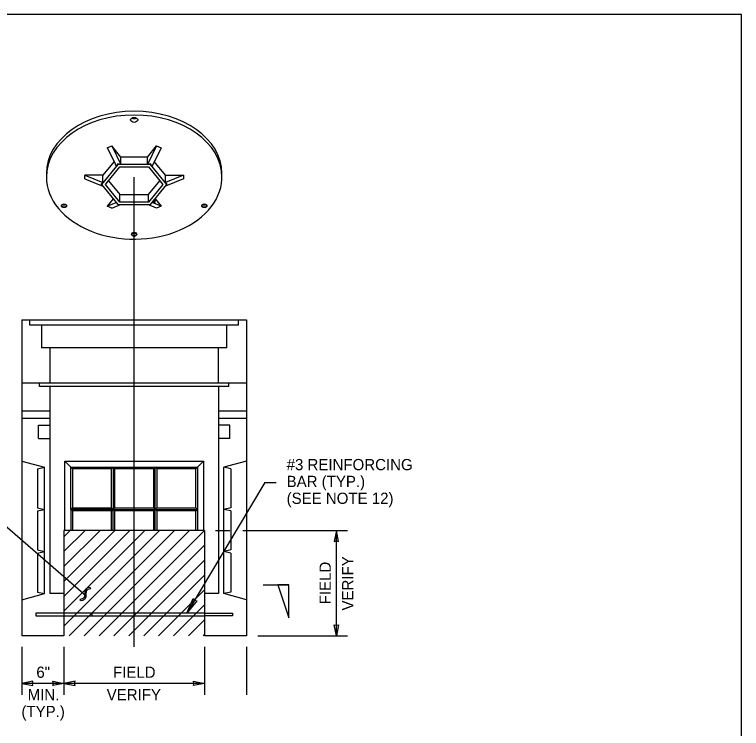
# Model space of a CAD drawing. Extents: x 99862 to 103151, y 100000 to 105076.
# Drawn here: x 102116 to 103151, y 104058 to 105076 of the extents above; entities that cross this region are included whole.
import ezdxf

# ---------------------------------------------------------------- set-up
doc = ezdxf.new("R2010")
doc.units = 0
for name, color, linetype in [('Level 1', 7, 'Continuous'), ('Level 10', 7, 'Continuous'), ('Level 12', 7, 'Continuous'), ('Level 14', 7, 'Continuous'), ('Level 15', 7, 'Continuous'), ('Level 2', 7, 'Continuous'), ('Level 20', 7, 'Continuous'), ('Level 21', 7, 'Continuous'), ('Level 3', 7, 'Continuous'), ('Level 60', 7, 'Continuous')]:
    doc.layers.add(name, color=color, linetype=linetype)

msp = doc.modelspace()

# ---------------------------------------------------------------- linework, layer by layer
at = {"layer": 'Level 1'}
msp.add_lwpolyline([(99862, 102999.5), (103151, 102999.5), (103151, 105075.5), (99862, 105075.5)], close=True, dxfattribs=at)
at = {"layer": 'Level 10'}
for p, q in [((102126.2, 104640.5), (102126.2, 104550.5)), ((102126.2, 104640.5), (102446.2, 104640.5)), ((102137.5, 104633), (102137.5, 104640.5)), ((102435, 104633), (102435, 104640.5)), ((102446.2, 104640.5), (102446.2, 104550.5)), ((102435, 104633), (102137.5, 104633)), ((102154.4, 104633), (102154.4, 104600.5)), ((102418.1, 104600.5), (102418.1, 104633)), ((102418.1, 104600.5), (102154.4, 104600.5)), ((102166.2, 104600.5), (102166.2, 104550.5)), ((102406.2, 104550.5), (102406.2, 104600.5)), ((102151.2, 104545.5), (102151.2, 104550.5)), ((102421.2, 104545.5), (102421.2, 104550.5)), ((102421.2, 104545.5), (102151.2, 104545.5))]:
    msp.add_line(p, q, dxfattribs=at)
at = {"layer": 'Level 12'}
for p, q in [((102247.9, 104885.5), (102254.4, 104888.2)), ((102247.9, 104885.5), (102257.5, 104865.9)), ((102267.2, 104872.5), (102254.4, 104888.2)), ((102254.4, 104888.2), (102267.2, 104862)), ((102305.2, 104872.5), (102318, 104888.2)), ((102318, 104888.2), (102305.2, 104862)), ((102324.5, 104885.5), (102311.7, 104859.3)), ((102318, 104888.2), (102324.5, 104885.5)), ((102267.2, 104862), (102267.2, 104872.5)), ((102305.2, 104872.5), (102267.2, 104872.5)), ((102305.2, 104862), (102305.2, 104872.5)), ((102262.9, 104861.9), (102239.6, 104833.3)), ((102257.5, 104865.9), (102241.8, 104846.6)), ((102257.5, 104865.9), (102260.7, 104859.3)), ((102262.9, 104862.9), (102260.7, 104859.3)), ((102262.9, 104861.9), (102262.9, 104862.9)), ((102267.2, 104862), (102262.9, 104862.9)), ((102309.5, 104861.9), (102262.9, 104861.9)), ((102309.5, 104862.9), (102305.2, 104862)), ((102311.7, 104859.3), (102309.5, 104862.9)), ((102309.5, 104861.9), (102309.5, 104862.9)), ((102332.9, 104833.3), (102309.5, 104861.9)), ((102330.7, 104846.6), (102314.9, 104865.9)), ((102245.4, 104833.3), (102265.8, 104858.3)), ((102265.8, 104858.3), (102306.7, 104858.3)), ((102306.7, 104858.3), (102327.1, 104833.3)), ((102161.2, 104849.2), (102161.2, 104843.9)), ((102216.1, 104841.3), (102216.1, 104846.6)), ((102241.8, 104846.6), (102216.1, 104846.6)), ((102216.1, 104846.6), (102241.8, 104836.1)), ((102216.1, 104841.3), (102241.6, 104830.9)), ((102241.8, 104836.1), (102241.8, 104846.6)), ((102356.3, 104846.6), (102330.7, 104836.1)), ((102330.7, 104836.1), (102330.7, 104846.6)), ((102330.7, 104846.6), (102356.3, 104846.6)), ((102356.3, 104841.3), (102330.9, 104830.9)), ((102356.3, 104846.6), (102356.3, 104841.3)), ((102411.2, 104843.9), (102411.2, 104849.2)), ((102241.8, 104836.1), (102239.6, 104834.3)), ((102239.6, 104833.3), (102239.6, 104834.3)), ((102239.6, 104833.3), (102262.9, 104804.7)), ((102265.8, 104808.3), (102245.4, 104833.3)), ((102249.7, 104838.6), (102265.8, 104818.9)), ((102306.7, 104818.9), (102322.8, 104838.6)), ((102327.1, 104833.3), (102306.7, 104808.3)), ((102309.5, 104804.7), (102332.9, 104833.3)), ((102332.9, 104834.3), (102330.7, 104836.1)), ((102332.9, 104833.3), (102332.9, 104834.3)), ((102256.4, 104812.7), (102247.9, 104802.3)), ((102265.8, 104808.3), (102265.8, 104818.9)), ((102265.8, 104818.9), (102306.7, 104818.9)), ((102306.7, 104808.3), (102306.7, 104818.9)), ((102316, 104812.7), (102324.5, 104802.3)), ((102182.6, 104804), (102182.6, 104803.1)), ((102190.1, 104803.1), (102190.1, 104804)), ((102247.9, 104802.3), (102260.7, 104807.5)), ((102254.4, 104799.6), (102247.9, 104802.3)), ((102254.4, 104799.6), (102266.9, 104804.7)), ((102262.9, 104804.7), (102309.5, 104804.7)), ((102306.7, 104808.3), (102265.8, 104808.3)), ((102318, 104799.6), (102305.5, 104804.7)), ((102324.5, 104802.3), (102311.8, 104807.5)), ((102315.7, 104807.6), (102315.7, 104807.6)), ((102324.5, 104802.3), (102318, 104799.6)), ((102382.3, 104804), (102382.3, 104803.1)), ((102389.8, 104803.1), (102389.8, 104804)), ((102282.5, 104763.3), (102282.5, 104762.4)), ((102290, 104762.4), (102290, 104763.3))]:
    msp.add_line(p, q, dxfattribs=at)
for centre, major_axis, ratio, start_param, end_param in [((102286.2, 104849.2), (-125, 0), 0.707107, 3.141593, 6.283185), ((102286.2, 104843.9), (-125, 0), 0.707107, 3.141593, 6.283185), ((102286.2, 104930.7), (-5, 0), 0.707107, 0.848062, 2.293531), ((102286.2, 104843.9), (-125, 0), 0.707107, 0, 3.171597), ((102314.3, 104811.1), (1.42, -3.47), 0.353553, 5.001419, 7.945203), ((102186.4, 104804), (3.75, 0), 0.707107, 3.309041, 6.115737), ((102186.4, 104808.4), (-5.94, 0), 0.707107, 1.054225, 2.087368), ((102386.1, 104804), (3.75, 0), 0.707107, 3.309041, 6.115737), ((102386.1, 104808.4), (-5.94, 0), 0.707107, 1.054225, 2.087368), ((102286.2, 104763.3), (3.75, 0), 0.707107, 3.309041, 6.115737), ((102286.2, 104767.7), (-5.94, 0), 0.707107, 1.054225, 2.087368)]:
    msp.add_ellipse(centre, major_axis=major_axis, ratio=ratio, start_param=start_param, end_param=end_param, dxfattribs=at)
for centre, major_axis in [((102286.2, 104925.4), (-5, 0)), ((102186.4, 104803.1), (-3.75, 0)), ((102386.1, 104803.1), (-3.75, 0)), ((102286.2, 104762.4), (-3.75, 0))]:
    msp.add_ellipse(centre, major_axis=major_axis, ratio=0.707107, dxfattribs=at)
at = {"layer": 'Level 14'}
for p, q in [((102186.2, 104222.4), (102146.2, 104222.4)), ((102146.2, 104222.4), (102146.2, 104218.6)), ((102226.2, 104222.4), (102186.2, 104222.4)), ((102386.2, 104222.4), (102226.2, 104222.4)), ((102226.2, 104218.6), (102226.2, 104222.4)), ((102386.2, 104222.4), (102426.2, 104222.4)), ((102426.2, 104222.4), (102426.2, 104218.6)), ((102146.2, 104218.6), (102186.2, 104218.6)), ((102186.2, 104218.6), (102226.2, 104218.6)), ((102226.2, 104218.6), (102386.2, 104218.6)), ((102426.2, 104218.6), (102386.2, 104218.6))]:
    msp.add_line(p, q, dxfattribs=at)
at = {"layer": 'Level 15'}
for p, q in [((102286.2, 104174.5), (102286.2, 104843.9)), ((102472.5, 104408.8), (102361, 104222.4)), ((102472.5, 104408.8), (102488.5, 104408.8)), ((102217.7, 104246.8), (102098.6, 104350.4)), ((102402.2, 104340.5), (102422.3, 104340.5)), ((102441, 104340.5), (102590.2, 104340.5)), ((102574.2, 104190.5), (102574.2, 104340.5)), ((102215.9, 104253.1), (102215.5, 104248.7)), ((102216.8, 104255.7), (102215.9, 104253.1)), ((102217.9, 104257.1), (102216.8, 104255.7)), ((102217.7, 104246.5), (102218, 104250.6)), ((102219.3, 104258.1), (102217.9, 104257.1)), ((102218, 104250.6), (102218.2, 104253.1)), ((102218.2, 104253.1), (102218.8, 104254.9)), ((102218.8, 104254.9), (102219.7, 104256)), ((102220.9, 104258.7), (102219.3, 104258.1)), ((102219.7, 104256), (102220.8, 104256.8)), ((102220.8, 104256.8), (102222.4, 104257.4)), ((102222.9, 104259), (102220.9, 104258.7)), ((102222.4, 104257.4), (102224.7, 104257.9)), ((102224.7, 104257.9), (102222.9, 104259)), ((102212.5, 104243), (102208.9, 104242)), ((102208.9, 104242), (102210.7, 104240.9)), ((102210.7, 104240.9), (102212.9, 104241.3)), ((102213.9, 104243.8), (102212.5, 104243)), ((102212.9, 104241.3), (102214.5, 104241.9)), ((102214.8, 104244.9), (102213.9, 104243.8)), ((102214.5, 104241.9), (102215.8, 104242.9)), ((102215.3, 104246.3), (102214.8, 104244.9)), ((102215.5, 104248.7), (102215.3, 104246.3)), ((102215.8, 104242.9), (102216.8, 104244.2)), ((102216.8, 104244.2), (102217.7, 104246.5)), ((102462.2, 104190.5), (102590.2, 104190.5)), ((102126.2, 104174.5), (102126.2, 104106.5)), ((102186.2, 104174.5), (102186.2, 104106.5)), ((102386.2, 104174.5), (102386.2, 104106.5)), ((102446.2, 104174.5), (102446.2, 104106.5)), ((102186.2, 104122.5), (102126.2, 104122.5)), ((102386.2, 104122.5), (102186.2, 104122.5))]:
    msp.add_line(p, q, dxfattribs=at)
for points in [[(102574.2, 104340.5), (102571.1, 104324.8), (102574.2, 104325.5), (102577.3, 104324.8)], [(102361, 104222.4), (102370.2, 104243.5), (102372.2, 104241.1), (102375.3, 104240.4)], [(102574.2, 104190.5), (102571.1, 104206.2), (102574.2, 104205.5), (102577.3, 104206.2)], [(102126.2, 104122.5), (102142, 104119.4), (102141.2, 104122.5), (102142, 104125.6)], [(102186.2, 104122.5), (102170.5, 104119.4), (102171.2, 104122.5), (102170.5, 104125.6)], [(102186.2, 104122.5), (102202, 104119.4), (102201.2, 104122.5), (102202, 104125.6)], [(102386.2, 104122.5), (102370.5, 104119.4), (102371.2, 104122.5), (102370.5, 104125.6)]]:
    msp.add_lwpolyline(points, close=True, dxfattribs=at)
at = {"layer": 'Level 2'}
for p, q in [((102126.2, 104550.5), (102126.2, 104190.5)), ((102446.2, 104550.5), (102446.2, 104190.5)), ((102166.2, 104545.5), (102166.2, 104250.5)), ((102406.2, 104545.5), (102406.2, 104250.5)), ((102126.2, 104510.5), (102126.2, 104500.5)), ((102166.2, 104510.5), (102126.2, 104510.5)), ((102166.2, 104510.5), (102166.2, 104500.5)), ((102406.2, 104510.5), (102406.2, 104500.5)), ((102446.2, 104510.5), (102406.2, 104510.5)), ((102446.2, 104510.5), (102446.2, 104500.5)), ((102126.2, 104500.5), (102166.2, 104500.5)), ((102406.2, 104500.5), (102446.2, 104500.5)), ((102150, 104490.5), (102166.2, 104490.5)), ((102150, 104471.7), (102150, 104490.5)), ((102422.5, 104490.5), (102406.2, 104490.5)), ((102422.5, 104471.7), (102422.5, 104490.5)), ((102150, 104471.7), (102166.2, 104471.7)), ((102422.5, 104471.7), (102406.2, 104471.7)), ((102126.2, 104439.2), (102158.7, 104430.5)), ((102187.5, 104340.5), (102187.5, 104439.2)), ((102187.5, 104439.2), (102196.2, 104430.5)), ((102187.5, 104439.2), (102384.9, 104439.2)), ((102384.9, 104439.2), (102376.2, 104430.5)), ((102384.9, 104439.2), (102384.9, 104340.5)), ((102446.2, 104439.2), (102413.7, 104430.5)), ((102148.7, 104428.3), (102158.7, 104430.5)), ((102148.7, 104428.3), (102148.7, 104372.7)), ((102158.7, 104370.5), (102158.7, 104430.5)), ((102196.2, 104370.5), (102196.2, 104430.5)), ((102196.2, 104430.5), (102256.2, 104430.5)), ((102198.4, 104428.3), (102196.2, 104430.5)), ((102254, 104428.3), (102198.4, 104428.3)), ((102198.4, 104428.3), (102198.4, 104372.7)), ((102254, 104428.3), (102256.2, 104430.5)), ((102254, 104372.7), (102254, 104428.3)), ((102256.2, 104430.5), (102316.2, 104430.5)), ((102256.2, 104430.5), (102256.2, 104370.5)), ((102258.4, 104428.3), (102256.2, 104430.5)), ((102258.4, 104428.3), (102258.4, 104372.7)), ((102314, 104428.3), (102258.4, 104428.3)), ((102314, 104428.3), (102316.2, 104430.5)), ((102314, 104372.7), (102314, 104428.3)), ((102316.2, 104370.5), (102316.2, 104430.5)), ((102316.2, 104430.5), (102376.2, 104430.5)), ((102318.4, 104428.3), (102316.2, 104430.5)), ((102374, 104428.3), (102318.4, 104428.3)), ((102318.4, 104428.3), (102318.4, 104372.7)), ((102374, 104428.3), (102376.2, 104430.5)), ((102374, 104372.7), (102374, 104428.3)), ((102376.2, 104430.5), (102376.2, 104370.5)), ((102423.7, 104428.3), (102413.7, 104430.5)), ((102413.7, 104370.5), (102413.7, 104430.5)), ((102423.7, 104428.3), (102423.7, 104372.7)), ((102148.7, 104372.7), (102158.7, 104370.5)), ((102148.7, 104368.3), (102158.7, 104370.5)), ((102148.7, 104368.3), (102148.7, 104312.7)), ((102158.7, 104310.5), (102158.7, 104370.5)), ((102198.4, 104372.7), (102196.2, 104370.5)), ((102256.2, 104370.5), (102196.2, 104370.5)), ((102196.2, 104370.5), (102196.2, 104340.5)), ((102198.4, 104368.3), (102196.2, 104370.5)), ((102198.4, 104372.7), (102254, 104372.7)), ((102198.4, 104368.3), (102198.4, 104340.5)), ((102254, 104368.3), (102198.4, 104368.3)), ((102254, 104372.7), (102256.2, 104370.5)), ((102254, 104368.3), (102256.2, 104370.5)), ((102254, 104340.5), (102254, 104368.3)), ((102258.4, 104372.7), (102256.2, 104370.5)), ((102258.4, 104368.3), (102256.2, 104370.5)), ((102256.2, 104340.5), (102256.2, 104370.5)), ((102256.2, 104370.5), (102316.2, 104370.5)), ((102258.4, 104372.7), (102314, 104372.7)), ((102258.4, 104368.3), (102258.4, 104340.5)), ((102314, 104368.3), (102258.4, 104368.3)), ((102314, 104372.7), (102316.2, 104370.5)), ((102314, 104368.3), (102316.2, 104370.5)), ((102314, 104340.5), (102314, 104368.3)), ((102318.4, 104372.7), (102316.2, 104370.5)), ((102318.4, 104368.3), (102316.2, 104370.5)), ((102316.2, 104340.5), (102316.2, 104370.5)), ((102316.2, 104370.5), (102376.2, 104370.5)), ((102318.4, 104372.7), (102374, 104372.7)), ((102374, 104368.3), (102318.4, 104368.3)), ((102318.4, 104368.3), (102318.4, 104340.5)), ((102374, 104372.7), (102376.2, 104370.5)), ((102374, 104368.3), (102376.2, 104370.5)), ((102374, 104340.5), (102374, 104368.3)), ((102376.2, 104370.5), (102376.2, 104340.5)), ((102423.7, 104372.7), (102413.7, 104370.5)), ((102413.7, 104310.5), (102413.7, 104370.5)), ((102423.7, 104368.3), (102413.7, 104370.5)), ((102423.7, 104368.3), (102423.7, 104312.7)), ((102186.2, 104340.5), (102186.2, 104190.5)), ((102386.2, 104340.5), (102186.2, 104340.5)), ((102386.2, 104340.5), (102386.2, 104190.5)), ((102148.7, 104312.7), (102158.7, 104310.5)), ((102423.7, 104312.7), (102413.7, 104310.5)), ((102148.7, 104308.3), (102158.7, 104310.5)), ((102148.7, 104308.3), (102148.7, 104252.7)), ((102158.7, 104250.5), (102158.7, 104310.5)), ((102423.7, 104308.3), (102413.7, 104310.5)), ((102413.7, 104250.5), (102413.7, 104310.5)), ((102423.7, 104308.3), (102423.7, 104252.7)), ((102126.2, 104241.8), (102158.7, 104250.5)), ((102148.7, 104252.7), (102158.7, 104250.5)), ((102186.2, 104250.5), (102166.2, 104250.5)), ((102406.2, 104250.5), (102386.2, 104250.5)), ((102423.7, 104252.7), (102413.7, 104250.5)), ((102446.2, 104241.8), (102413.7, 104250.5)), ((102186.2, 104190.5), (102126.2, 104190.5)), ((102446.2, 104190.5), (102386.2, 104190.5))]:
    msp.add_line(p, q, dxfattribs=at)
at = {"layer": 'Level 20'}
msp.add_line((102469.8, 104262.9), (102506.3, 104262.9), dxfattribs=at)
msp.add_lwpolyline([(102490.8, 104262.9), (102506.3, 104216.1), (102506.3, 104262.9)], close=True, dxfattribs=at)
at = {"layer": 'Level 21'}
for p, q in [((102186.2, 104331.5), (102195.3, 104340.5)), ((102186.2, 104310.3), (102216.5, 104340.5)), ((102186.2, 104289), (102237.7, 104340.5)), ((102186.2, 104267.8), (102258.9, 104340.5)), ((102186.2, 104246.6), (102280.1, 104340.5)), ((102186.2, 104225.4), (102301.3, 104340.5)), ((102186.2, 104204.2), (102322.5, 104340.5)), ((102193.7, 104190.5), (102343.7, 104340.5)), ((102215, 104190.5), (102365, 104340.5)), ((102236.2, 104190.5), (102386.2, 104340.5)), ((102257.4, 104190.5), (102386.2, 104319.3)), ((102278.6, 104190.5), (102386.2, 104298.1)), ((102299.8, 104190.5), (102386.2, 104276.9)), ((102321, 104190.5), (102386.2, 104255.7)), ((102342.2, 104190.5), (102386.2, 104234.5)), ((102363.5, 104190.5), (102386.2, 104213.3)), ((102384.7, 104190.5), (102386.2, 104192.1))]:
    msp.add_line(p, q, dxfattribs=at)
at = {"layer": 'Level 3'}
msp.add_line((102446.2, 104550.5), (102126.2, 104550.5), dxfattribs=at)
at = {"layer": 'Level 60'}
msp.add_line((103151, 105075.5), (103151, 105075.5), dxfattribs=at)

# ---------------------------------------------------------------- texts
at = {"layer": 'Level 20'}
for s, p in [('#3 REINFORCING', (102503.3, 104426.3)), ('BAR (TYP.) ', (102503.3, 104402.3)), ('(SEE NOTE 12)', (102503.3, 104378.3)), ('6"', (102146.9, 104130.5)), ('FIELD', (102256, 104130.5)), ('MIN.', (102134.5, 104098.5)), ('VERIFY', (102247.1, 104098.5)), ('(TYP.)', (102125.7, 104074.5))]:
    msp.add_text(s, height=16, dxfattribs=at).set_placement(p)
for s, p in [('VERIFY', (102598.2, 104226.4)), ('FIELD', (102566.2, 104235.3))]:
    msp.add_text(s, height=16, rotation=90, dxfattribs=at).set_placement(p)

doc.saveas('drawing.dxf')
